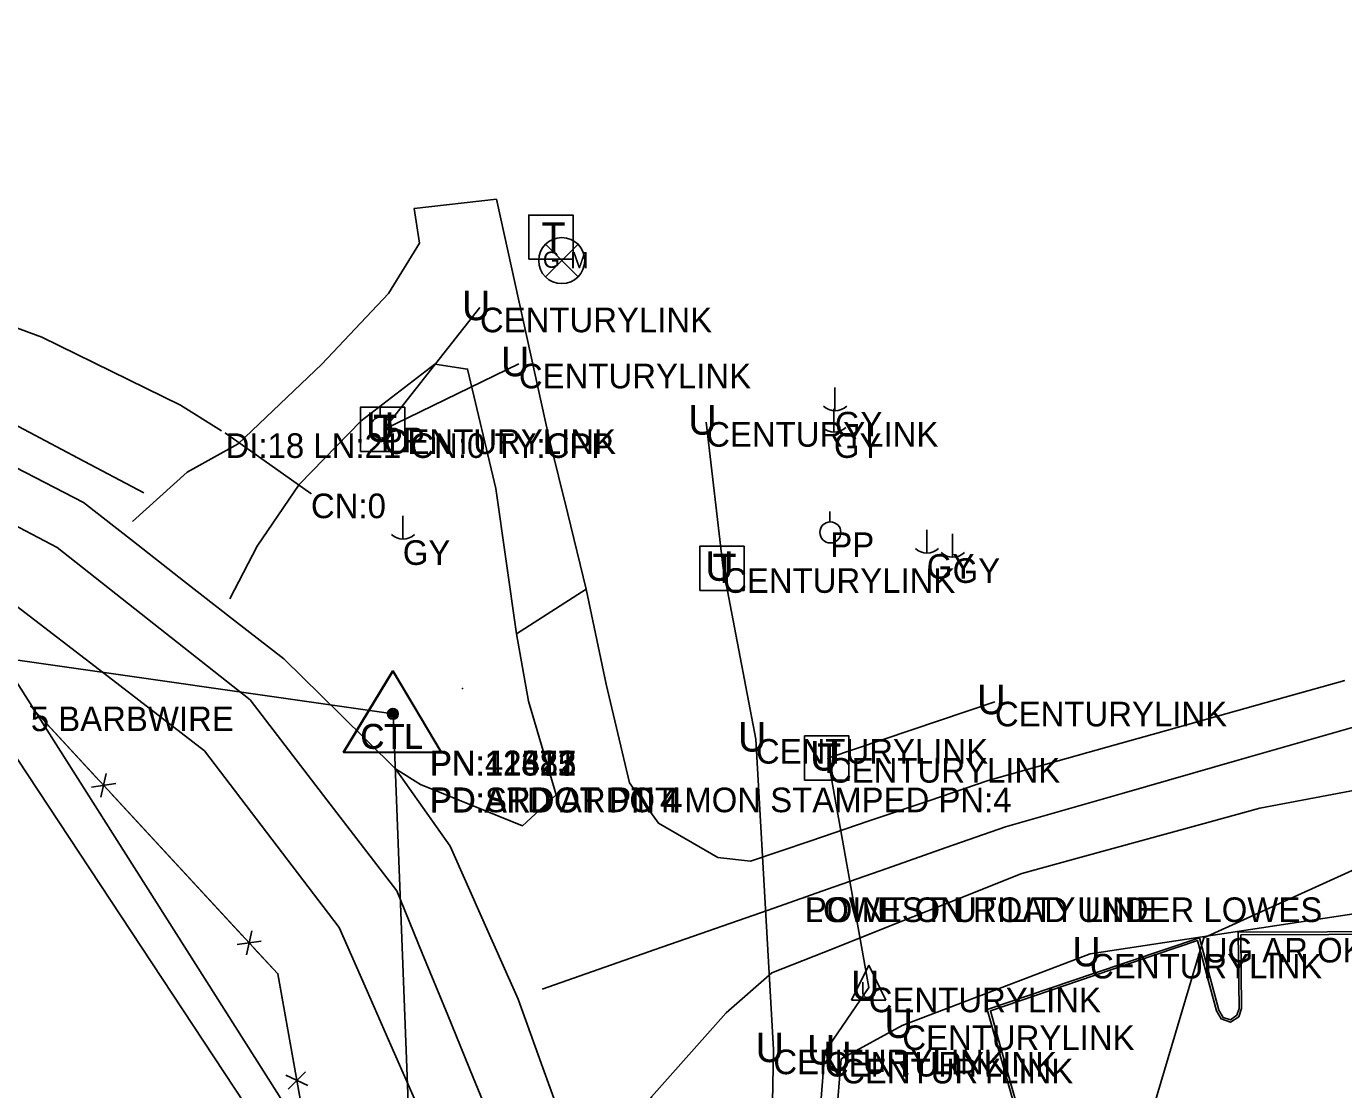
# Model space of a CAD drawing. Extents: x 675481 to 678499, y 212715 to 215285.
# Drawn here: x 677784.7 to 678052.3, y 214487.7 to 214703.7 of the extents above; entities that cross this region are included whole.
import ezdxf

# ---------------------------------------------------------------- set-up
doc = ezdxf.new("R2010")
doc.units = 0
for name, color, linetype in [('Default', 7, 'Continuous'), ('S_BASELINE', 7, 'Continuous'), ('S_CURB', 7, 'Continuous'), ('S_DITCHLINE', 7, 'Continuous'), ('S_DRG_PT_SYM', 7, 'Continuous'), ('S_DRIVEWAY', 7, 'Continuous'), ('S_EDGE_CONCRETE', 7, 'Continuous'), ('S_EDGE_PAVEMENT', 7, 'Continuous'), ('S_ELECTRIC_UTILITIES_ANNOT', 7, 'Continuous'), ('S_FENCE', 7, 'Continuous'), ('S_FENCE_ANNOT', 7, 'Continuous'), ('S_FIBER_OPTIC_CABLE', 7, 'Continuous'), ('S_GAS_UTILITIES', 7, 'Continuous'), ('S_GAS_UTILITIES_ANNOT', 7, 'Continuous'), ('S_GRD_PT_SYM', 7, 'Continuous'), ('S_MSC_PT_SYM', 7, 'Continuous'), ('S_PAVEMENT_CROWN', 7, 'Continuous'), ('S_PRIMARY_CTL', 7, 'Continuous'), ('S_PRIMARY_CTL_ANNOT', 7, 'Continuous'), ('S_SHOULDER', 7, 'Continuous'), ('S_SIDE_DRAIN', 7, 'Continuous'), ('S_SIDE_DRAIN_ANNOT', 7, 'Continuous'), ('S_SURVEY_TEXT_ANNOT', 7, 'Continuous'), ('S_TELEPHONE_UTILITIES', 7, 'Continuous'), ('S_TELEPHONE_UTILITIES_ANNOT', 7, 'Continuous'), ('S_UNDERGROUND_CABLE', 7, 'Continuous'), ('S_UNDERGROUND_CABLE_ANNOT', 7, 'Continuous'), ('S_UTILITY_POLE', 7, 'Continuous'), ('S_UTILITY_POLE_ANNOT', 7, 'Continuous'), ('S_UTL_PT_SYM', 7, 'Continuous')]:
    doc.layers.add(name, color=color, linetype=linetype)

msp = doc.modelspace()

# ---------------------------------------------------------------- linework, layer by layer
at = {"layer": 'S_BASELINE'}
for p, q in [((676879.32, 214703.75), (677859.17, 214564.08)), ((677859.17, 214564.08), (677899.68, 213513.2))]:
    msp.add_line(p, q, dxfattribs=at)
at = {"layer": 'S_CURB'}
msp.add_lwpolyline([(678067.09, 214519.88), (678048.97, 214519.79), (678030.85, 214519.69), (678031.05, 214504.17), (678030.55, 214502.87), (678029.27, 214501.93), (678027.8, 214502.35), (678026.93, 214503.85), (678022.99, 214518.57), (678001.43, 214511.29), (677979.87, 214504.01), (677983.38, 214491.58), (677986.88, 214479.15)], dxfattribs=at)
at = {"layer": 'S_DITCHLINE'}
msp.add_lwpolyline([(677589.25, 214686.88), (677606.27, 214683.2), (677623.28, 214679.51), (677640.3, 214675.82), (677657.32, 214672.14), (677676.79, 214670.17), (677696.26, 214668.21), (677712.87, 214665.13), (677729.48, 214662.05), (677744.05, 214656.69), (677758.63, 214651.33), (677773.21, 214645.97), (677787.78, 214640.6), (677801.89, 214633.68), (677815.99, 214626.75), (677824.32, 214621.54)], dxfattribs=at)
at = {"layer": 'S_DRG_PT_SYM'}
for points in [[(677825.12, 214621.06), (677825.12, 214621.11), (677825.12, 214621.06), (677825.07, 214621.06), (677825.12, 214621.06), (677825.12, 214621.01), (677825.12, 214621.06), (677825.17, 214621.06)], [(677842.47, 214608.82), (677842.47, 214608.87), (677842.47, 214608.82), (677842.42, 214608.82), (677842.47, 214608.82), (677842.47, 214608.77), (677842.47, 214608.82), (677842.52, 214608.82)]]:
    msp.add_lwpolyline(points, dxfattribs=at)
at = {"layer": 'S_DRIVEWAY'}
for points in [[(677806.21, 214603.12), (677817.31, 214613.14), (677827.67, 214618.93), (677844.68, 214635.12), (677858.25, 214649.45), (677864.51, 214659.69), (677863.44, 214666.72), (677880.19, 214668.64)], [(677880.19, 214668.64), (677885.54, 214644.32), (677890.88, 214620.01), (677894.63, 214604.71), (677898.38, 214589.41), (677884.21, 214580.3), (677882.11, 214595.08), (677880, 214609.86), (677874.3, 214634.11), (677867.66, 214635.13), (677852.66, 214623.62), (677840.11, 214610.66), (677831.52, 214598.12), (677825.98, 214587.46)]]:
    msp.add_lwpolyline(points, dxfattribs=at)
at = {"layer": 'S_EDGE_CONCRETE'}
msp.add_lwpolyline([(678067.14, 214519.33), (678049.27, 214519.23), (678031.4, 214519.14), (678031.55, 214504.2), (678030.96, 214502.52), (678029.27, 214501.45), (678027.36, 214502.07), (678026.47, 214503.73), (678022.61, 214518.01), (678001.57, 214510.88), (677980.52, 214503.75), (677983.94, 214491.55), (677987.36, 214479.34)], dxfattribs=at)
at = {"layer": 'S_EDGE_PAVEMENT'}
for points in [[(677752.72, 214629.55), (677774.48, 214618.26), (677796.25, 214606.98)], [(677836.94, 214575.26), (677826.77, 214583.19), (677816.59, 214591.12), (677806.42, 214599.05), (677796.25, 214606.98)], [(677898.38, 214589.41), (677902.44, 214570.13)], [(677820.84, 214556.56), (677801.28, 214571.63), (677781.72, 214586.69)], [(677884.21, 214580.3), (677886.65, 214566.67)], [(677836.94, 214575.26), (677848.31, 214564.09), (677859.68, 214552.92), (677870.73, 214537.2), (677877.66, 214521.64), (677884.59, 214506.09), (677889.61, 214492.12), (677894.63, 214478.16), (677897.75, 214464.3), (677900.87, 214450.43), (677901.87, 214437.41), (677902.87, 214424.38), (677903, 214411.76), (677903.13, 214399.15), (677903.26, 214386.53), (677903.39, 214373.91), (677903.35, 214355.89), (677903.32, 214337.87), (677902, 214337.89), (677901.46, 214323.49), (677900.93, 214309.09), (677900.4, 214294.69)], [(677902.44, 214570.13), (677907.16, 214550.08), (677913.05, 214541.85), (677925.12, 214534.9), (677931.76, 214534.13), (677943.83, 214538.22), (677955.9, 214542.32), (677967.97, 214546.42), (677980.04, 214550.51), (677992.12, 214553.9), (678004.19, 214557.3), (678016.27, 214560.69), (678028.35, 214564.08), (678040.42, 214567.48), (678052.5, 214570.87)], [(677864.7, 214549.69), (677885.45, 214541.32), (677892.32, 214547.63), (677886.65, 214566.67)], [(677820.84, 214556.56), (677834.52, 214538.62), (677848.19, 214520.68), (677853.46, 214508.7), (677858.73, 214496.72), (677864, 214484.74), (677869.27, 214472.76), (677871.58, 214459.86), (677873.89, 214446.96), (677876.2, 214434.06), (677878.5, 214421.16), (677879.53, 214397.37), (677880.55, 214373.58), (677879.91, 214348.66), (677879.26, 214323.75), (677878.61, 214298.83)], [(677859.68, 214552.92), (677864.7, 214549.69)], [(677902.14, 214462.33), (677906.9, 214474.28), (677911.66, 214486.23), (677926.85, 214503.34), (677936.11, 214511.45), (677948.81, 214516.49), (677961.5, 214521.54), (677974.19, 214526.58), (677986.88, 214531.62), (677998.97, 214534.94), (678011.07, 214538.25), (678023.16, 214541.57), (678035.25, 214544.88), (678054.98, 214548.6)]]:
    msp.add_lwpolyline(points, dxfattribs=at)
at = {"layer": 'S_FENCE'}
for p, q in [((677785.56, 214565.55), (677835.73, 214511.24)), ((677800.89, 214551.97), (677799.81, 214547.11)), ((677800.89, 214551.97), (677799.81, 214547.11)), ((677800.89, 214551.97), (677799.81, 214547.11)), ((677797.88, 214549.19), (677802.81, 214549.89)), ((677797.88, 214549.19), (677802.81, 214549.89)), ((677797.88, 214549.19), (677802.81, 214549.89)), ((677830.46, 214519.96), (677829.38, 214515.09)), ((677830.46, 214519.96), (677829.38, 214515.09)), ((677830.46, 214519.96), (677829.38, 214515.09)), ((677827.45, 214517.18), (677832.39, 214517.87)), ((677827.45, 214517.18), (677832.39, 214517.87)), ((677827.45, 214517.18), (677832.39, 214517.87)), ((677835.73, 214511.24), (677843.18, 214469.62)), ((677837.34, 214490.63), (677841.87, 214488.53)), ((677837.34, 214490.63), (677841.87, 214488.53)), ((677837.34, 214490.63), (677841.87, 214488.53)), ((677841.37, 214491.36), (677837.84, 214487.81)), ((677841.37, 214491.36), (677837.84, 214487.81)), ((677841.37, 214491.36), (677837.84, 214487.81))]:
    msp.add_line(p, q, dxfattribs=at)
for points in [[(677785.56, 214565.55), (677799, 214551)], [(677785.56, 214565.55), (677799, 214551)], [(677785.56, 214565.55), (677799, 214551)], [(677800.89, 214551.97), (677799.81, 214547.11)], [(677800.89, 214551.97), (677799.81, 214547.11)], [(677797.88, 214549.19), (677802.81, 214549.89)], [(677797.88, 214549.19), (677802.81, 214549.89)], [(677801.69, 214548.09), (677828.57, 214518.98)], [(677801.69, 214548.09), (677828.57, 214518.98)], [(677801.69, 214548.09), (677828.57, 214518.98)], [(677830.46, 214519.96), (677829.38, 214515.09)], [(677830.46, 214519.96), (677829.38, 214515.09)], [(677827.45, 214517.18), (677832.39, 214517.87)], [(677827.45, 214517.18), (677832.39, 214517.87)], [(677830.88, 214516.48), (677835.73, 214511.24)], [(677830.88, 214516.48), (677835.73, 214511.24)], [(677830.88, 214516.48), (677835.73, 214511.24)], [(677835.73, 214511.24), (677839.25, 214491.55)], [(677835.73, 214511.24), (677839.25, 214491.55)], [(677835.73, 214511.24), (677839.25, 214491.55)], [(677837.34, 214490.63), (677841.87, 214488.53)], [(677837.34, 214490.63), (677841.87, 214488.53)], [(677841.37, 214491.36), (677837.84, 214487.81)], [(677841.37, 214491.36), (677837.84, 214487.81)]]:
    msp.add_lwpolyline(points, dxfattribs=at)
at = {"layer": 'S_FIBER_OPTIC_CABLE'}
for p, q in [((677770.28, 214573.85), (677848.71, 214455.13)), ((677780.88, 214573.35), (677855.11, 214456.45))]:
    msp.add_line(p, q, dxfattribs=at)
at = {"layer": 'S_GAS_UTILITIES'}
for p, q in [((677890.11, 214652.85), (677896.73, 214659.46)), ((677890.11, 214659.46), (677896.73, 214652.85)), ((678060.85, 214535.39), (678023.84, 214518.55)), ((677939.09, 214232.8), (678023.84, 214518.55))]:
    msp.add_line(p, q, dxfattribs=at)
msp.add_circle((677893.42, 214656.15), 4.68, dxfattribs=at)
at = {"layer": 'S_GRD_PT_SYM'}
msp.add_lwpolyline([(677873.25, 214569.2), (677873.25, 214569.25), (677873.25, 214569.2), (677873.2, 214569.2), (677873.25, 214569.2), (677873.25, 214569.15), (677873.25, 214569.2), (677873.3, 214569.2)], dxfattribs=at)
at = {"layer": 'S_MSC_PT_SYM'}
for points in [[(677785.56, 214565.55), (677785.56, 214565.6), (677785.56, 214565.55), (677785.51, 214565.55), (677785.56, 214565.55), (677785.56, 214565.5), (677785.56, 214565.55), (677785.61, 214565.55)], [(677942.8, 214526.77), (677942.8, 214526.82), (677942.8, 214526.77), (677942.75, 214526.77), (677942.8, 214526.77), (677942.8, 214526.72), (677942.8, 214526.77), (677942.85, 214526.77)], [(677835.73, 214511.24), (677835.73, 214511.29), (677835.73, 214511.24), (677835.68, 214511.24), (677835.73, 214511.24), (677835.73, 214511.19), (677835.73, 214511.24), (677835.78, 214511.24)]]:
    msp.add_lwpolyline(points, dxfattribs=at)
at = {"layer": 'S_PAVEMENT_CROWN'}
for points in [[(677749.66, 214619.48), (677770.29, 214608.67), (677790.92, 214597.87)], [(677830.11, 214566.89), (677810.52, 214582.38), (677790.92, 214597.87)], [(677889.42, 214508.16), (677912.41, 214516.17), (677935.39, 214524.19), (677947.44, 214528.42), (677959.49, 214532.65), (677971.54, 214536.88), (677983.58, 214541.1), (678007.3, 214547.9), (678031.02, 214554.69), (678054.74, 214561.49), (678078.45, 214568.28), (678091.14, 214571.17), (678103.82, 214574.06), (678116.5, 214576.95), (678129.18, 214579.84), (678141.86, 214582.73), (678154.54, 214585.62), (678167.23, 214588.52), (678179.91, 214591.41), (678193.01, 214592.07), (678206.1, 214592.74), (678219.2, 214593.4), (678232.3, 214594.07)], [(677830.11, 214566.89), (677845, 214547.51), (677859.89, 214528.12), (677865.08, 214515.47), (677870.27, 214502.82), (677875.46, 214490.17), (677880.66, 214477.51), (677883.16, 214463.81), (677885.67, 214450.11), (677888.18, 214436.41), (677890.68, 214422.71), (677891.52, 214398.36), (677892.37, 214374.01), (677892.05, 214361.49), (677891.73, 214348.97), (677891.41, 214336.45), (677891.1, 214323.93), (677890.78, 214311.4), (677890.46, 214298.88)]]:
    msp.add_lwpolyline(points, dxfattribs=at)
at = {"layer": 'S_PRIMARY_CTL'}
for p, q in [((677859.07, 214572.79), (677849.04, 214556.28)), ((677859.09, 214572.77), (677849.06, 214556.26)), ((677859.14, 214572.81), (677849.1, 214556.29)), ((677859.13, 214572.74), (677849.1, 214556.22)), ((677859.13, 214572.72), (677849.1, 214556.21)), ((677859.14, 214572.81), (677849.11, 214556.3)), ((677859.16, 214572.73), (677849.12, 214556.21)), ((677859.17, 214572.78), (677849.14, 214556.27)), ((677859.18, 214572.77), (677849.14, 214556.26)), ((677859.07, 214572.79), (677868.9, 214556.28)), ((677859.09, 214572.77), (677868.92, 214556.26)), ((677859.13, 214572.74), (677868.95, 214556.22)), ((677859.13, 214572.72), (677868.95, 214556.21)), ((677859.14, 214572.81), (677868.97, 214556.3)), ((677859.14, 214572.81), (677868.96, 214556.29)), ((677859.16, 214572.73), (677868.98, 214556.21)), ((677859.17, 214572.78), (677869, 214556.27)), ((677859.18, 214572.77), (677869, 214556.26)), ((677849.04, 214556.28), (677868.9, 214556.28)), ((677849.06, 214556.26), (677868.92, 214556.26)), ((677849.1, 214556.29), (677868.96, 214556.29)), ((677849.1, 214556.22), (677868.95, 214556.22)), ((677849.1, 214556.21), (677868.95, 214556.21)), ((677849.11, 214556.3), (677868.97, 214556.3)), ((677849.12, 214556.21), (677868.98, 214556.21)), ((677849.14, 214556.27), (677869, 214556.27)), ((677849.14, 214556.26), (677869, 214556.26))]:
    msp.add_line(p, q, dxfattribs=at)
for centre, radius in [((677859.07, 214564.09), 1.04), ((677859.09, 214564.07), 1.04), ((677859.13, 214564.04), 1.04), ((677859.13, 214564.02), 1.04), ((677859.14, 214564.11), 1.04), ((677859.14, 214564.11), 1.04), ((677859.16, 214564.02), 1.04), ((677859.17, 214564.08), 1.04), ((677859.18, 214564.07), 1.04), ((677859.07, 214564.09), 0.609), ((677859.09, 214564.07), 0.609), ((677859.13, 214564.04), 0.609), ((677859.13, 214564.02), 0.609), ((677859.14, 214564.11), 0.609), ((677859.14, 214564.11), 0.609), ((677859.16, 214564.02), 0.609), ((677859.17, 214564.08), 0.609), ((677859.18, 214564.07), 0.609), ((677859.07, 214564.09), 0.344), ((677859.09, 214564.07), 0.344), ((677859.13, 214564.04), 0.344), ((677859.14, 214564.11), 0.344), ((677859.13, 214564.02), 0.344), ((677859.14, 214564.11), 0.344), ((677859.16, 214564.02), 0.344), ((677859.17, 214564.08), 0.344), ((677859.18, 214564.07), 0.344)]:
    msp.add_circle(centre, radius, dxfattribs=at)
at = {"layer": 'S_SHOULDER'}
msp.add_lwpolyline([(677593.42, 214672.21), (677606.23, 214665.21), (677629.5, 214662.49), (677652.77, 214659.76), (677665.57, 214656.94), (677678.38, 214654.11), (677691.18, 214651.28), (677703.99, 214648.45), (677716.79, 214645.62), (677729.6, 214642.79), (677742.4, 214639.96), (677755.21, 214637.13), (677768.54, 214630.09), (677781.88, 214623.04), (677795.21, 214615.99), (677808.55, 214608.95)], dxfattribs=at)
at = {"layer": 'S_SIDE_DRAIN'}
msp.add_line((677825.12, 214621.06), (677842.47, 214608.82), dxfattribs=at)
at = {"layer": 'S_TELEPHONE_UTILITIES'}
for points in [[(677886.72, 214656.41), (677886.72, 214665.41), (677895.72, 214665.41), (677895.72, 214656.41)], [(677852.52, 214617.35), (677852.52, 214626.35), (677861.52, 214626.35), (677861.52, 214617.35)], [(677921.47, 214589.13), (677921.47, 214598.13), (677930.47, 214598.13), (677930.47, 214589.13)], [(677942.77, 214550.57), (677942.77, 214559.57), (677951.77, 214559.57), (677951.77, 214550.57)]]:
    msp.add_lwpolyline(points, close=True, dxfattribs=at)
at = {"layer": 'S_UNDERGROUND_CABLE'}
for p, q in [((677857.25, 214621.87), (677876.79, 214646.59)), ((677857.25, 214621.87), (677884.71, 214635.2)), ((677926.2, 214593.65), (677922.76, 214623.34)), ((677932.86, 214558.95), (677926.2, 214593.65)), ((677947.5, 214555.09), (677981.42, 214566.52)), ((678313.93, 214562.77), (678000.75, 214515.3)), ((677936.41, 214495.85), (677932.86, 214558.95)), ((677955.79, 214508.44), (677947.5, 214555.09)), ((677962.61, 214500.76), (678000.75, 214515.3)), ((677955.79, 214512.98), (677952.27, 214505.89)), ((677955.79, 214512.98), (677959.28, 214505.89)), ((677946.88, 214495.38), (677955.79, 214508.44)), ((677954.59, 214507.13), (677954.59, 214509.57)), ((677956.95, 214509.57), (677956.95, 214507.13)), ((677952.27, 214505.89), (677959.28, 214505.89)), ((677955.21, 214506.47), (677954.59, 214507.13)), ((677956.41, 214506.47), (677955.21, 214506.47)), ((677956.95, 214507.13), (677956.41, 214506.47)), ((677950.17, 214493.98), (677962.61, 214500.76)), ((677935.63, 214453.9), (677936.41, 214495.85)), ((677943.45, 214453.24), (677946.88, 214495.38)), ((677946.68, 214452.08), (677950.17, 214493.98))]:
    msp.add_line(p, q, dxfattribs=at)
at = {"layer": 'S_UTILITY_POLE'}
for p, q in [((677948.9, 214630.36), (677948.9, 214625.63)), ((677856.55, 214624.37), (677856.55, 214626.48)), ((677948.69, 214626.02), (677948.69, 214621.29)), ((677861.11, 214604.28), (677861.11, 214599.55)), ((677947.87, 214603.08), (677947.87, 214605.18)), ((677967.56, 214601.45), (677967.56, 214596.72)), ((677972.82, 214600.61), (677972.82, 214595.88))]:
    msp.add_line(p, q, dxfattribs=at)
for centre in [(677856.67, 214622.23), (677947.99, 214600.93)]:
    msp.add_circle(centre, 2.13, dxfattribs=at)
for centre in [(677948.96, 214629.06), (677948.76, 214624.72), (677861.18, 214602.98), (677967.62, 214600.15), (677972.88, 214599.31)]:
    msp.add_arc(centre, 3.41, 226.3972, 313.6028, dxfattribs=at)
at = {"layer": 'S_UTL_PT_SYM'}
for points in [[(677942.81, 214526.77), (677942.81, 214526.82), (677942.81, 214526.77), (677942.76, 214526.77), (677942.81, 214526.77), (677942.81, 214526.72), (677942.81, 214526.77), (677942.86, 214526.77)], [(678023.84, 214518.55), (678023.84, 214518.6), (678023.84, 214518.55), (678023.79, 214518.55), (678023.84, 214518.55), (678023.84, 214518.5), (678023.84, 214518.55), (678023.89, 214518.55)], [(678023.84, 214518.55), (678023.84, 214518.6), (678023.84, 214518.55), (678023.79, 214518.55), (678023.84, 214518.55), (678023.84, 214518.5), (678023.84, 214518.55), (678023.89, 214518.55)]]:
    msp.add_lwpolyline(points, dxfattribs=at)

# ---------------------------------------------------------------- texts
at = {"layer": 'Default'}
for p in [(677873.16, 214644.05), (677881.08, 214632.65), (677919.13, 214620.79), (677853.62, 214619.32), (677853.62, 214619.32), (677922.57, 214591.1), (677977.79, 214563.98), (677929.23, 214556.4), (677943.87, 214552.54), (677997.12, 214512.76), (677997.12, 214512.76), (677952.16, 214505.9), (677958.98, 214498.21), (677932.78, 214493.31), (677943.25, 214492.83), (677946.54, 214491.43)]:
    msp.add_text('U', height=6, rotation=360, dxfattribs=at).set_placement(p)
at = {"layer": 'S_ELECTRIC_UTILITIES_ANNOT'}
msp.add_text('LOWEST UTILITY LINE', height=5, dxfattribs=at).set_placement((677942.81, 214521.77))
at = {"layer": 'S_FENCE_ANNOT'}
msp.add_text('5 BARBWIRE', height=5, dxfattribs=at).set_placement((677785.56, 214560.55))
at = {"layer": 'S_GAS_UTILITIES'}
for s, p in [('G', (677889.6, 214654.69)), ('M', (677895.16, 214654.59))]:
    msp.add_text(s, height=3.3, rotation=360, dxfattribs=at).set_placement(p)
at = {"layer": 'S_GAS_UTILITIES_ANNOT'}
msp.add_text('UG AR OK GAS CO', height=5, dxfattribs=at).set_placement((678023.84, 214513.55))
msp.add_text('UG AR OK GAS CO', height=5, dxfattribs=at).set_placement((678023.84, 214513.55))
at = {"layer": 'S_PRIMARY_CTL'}
for p in [(677852.49, 214557.01), (677852.5, 214556.99), (677852.54, 214556.96), (677852.54, 214556.95), (677852.55, 214557.03), (677852.55, 214557.03), (677852.57, 214556.95), (677852.59, 214557.01), (677852.59, 214556.99)]:
    msp.add_text('CTL', height=5, rotation=360, dxfattribs=at).set_placement(p)
at = {"layer": 'S_PRIMARY_CTL_ANNOT'}
for s, p in [('PN:11377', (677866.58, 214551.59)), ('PN:11312', (677866.59, 214551.57)), ('PN:12625', (677866.63, 214551.54)), ('PN:12583', (677866.63, 214551.52)), ('PN:11313', (677866.64, 214551.61)), ('PN:12527', (677866.64, 214551.61)), ('PN:12581', (677866.66, 214551.52)), ('PN:4', (677866.68, 214551.58)), ('PN:12413', (677866.68, 214551.57)), ('PD:ARDOT PT 4', (677866.58, 214544.09)), ('PD:ARDOT PN 4', (677866.59, 214544.07)), ('PD:ARDOT PN 4', (677866.63, 214544.04)), ('PD:ARDOT PN 4', (677866.63, 214544.02)), ('PD:ARDOT PN 4', (677866.64, 214544.11)), ('PD:ARDOT PN 4', (677866.64, 214544.11)), ('PD:ARDOT PN 4', (677866.66, 214544.02)), ('PD:STD ARDOT MON STAMPED PN:4', (677866.68, 214544.08)), ('PD:ARDOT PN 4', (677866.68, 214544.07))]:
    msp.add_text(s, height=5, dxfattribs=at).set_placement(p)
at = {"layer": 'S_SIDE_DRAIN_ANNOT'}
for s, p in [('DI:18 LN:21 CN:0 TY:CPP', (677825.12, 214616.06)), ('CN:0', (677842.47, 214603.82))]:
    msp.add_text(s, height=5, dxfattribs=at).set_placement(p)
at = {"layer": 'S_SURVEY_TEXT_ANNOT'}
msp.add_text('POINT ON ROAD UNDER LOWES', height=5, dxfattribs=at).set_placement((677942.8, 214521.77))
at = {"layer": 'S_TELEPHONE_UTILITIES'}
for p in [(677889.28, 214657.91), (677855.09, 214618.85), (677924.03, 214590.63), (677945.33, 214552.07)]:
    msp.add_text('T', height=6, rotation=360, dxfattribs=at).set_placement(p)
at = {"layer": 'S_TELEPHONE_UTILITIES_ANNOT'}
for p in [(677857.25, 214616.87), (677926.2, 214588.65), (677947.5, 214550.09)]:
    msp.add_text('CENTURYLINK', height=5, dxfattribs=at).set_placement(p)
at = {"layer": 'S_UNDERGROUND_CABLE_ANNOT'}
for p in [(677876.79, 214641.59), (677884.71, 214630.2), (677922.76, 214618.34), (677857.25, 214616.87), (677857.25, 214616.87), (677926.2, 214588.65), (677981.42, 214561.52), (677932.86, 214553.95), (677947.5, 214550.09), (678000.75, 214510.3), (678000.75, 214510.3), (677955.79, 214503.44), (677962.61, 214495.76), (677936.41, 214490.85), (677946.88, 214490.38), (677950.17, 214488.98)]:
    msp.add_text('CENTURYLINK', height=5, dxfattribs=at).set_placement(p)
at = {"layer": 'S_UTILITY_POLE_ANNOT'}
for s, p in [('GY', (677948.92, 214620.42)), ('PP', (677856.67, 214617.23)), ('GY', (677948.71, 214616.07)), ('GY', (677861.13, 214594.33)), ('PP', (677947.99, 214595.93)), ('GY', (677967.58, 214591.51)), ('GY', (677972.83, 214590.67)), ('CENTURYLINK', (677955.79, 214503.44))]:
    msp.add_text(s, height=5, dxfattribs=at).set_placement(p)

doc.saveas('drawing.dxf')
